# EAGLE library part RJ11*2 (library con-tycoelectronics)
RJ11 (Style 1 Shield / Style 2 Shield) Source: www.tycoelectronics.com .. ENG_DS_1654001_1099_RJ_L_0507.pdf
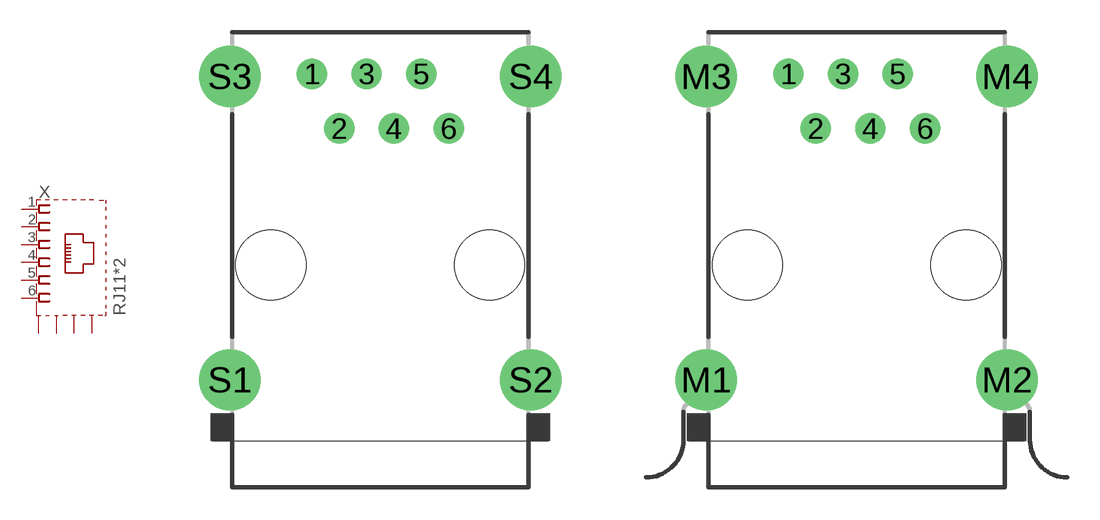
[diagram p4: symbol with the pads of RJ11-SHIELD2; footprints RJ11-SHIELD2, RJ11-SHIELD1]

Designator prefix X

## RJ11-2LC2-S (MPN: RJ11-2LC2-S; OC_FARNELL: unknown; OC_NEWARK: 16R6077), RJ11-4L2-S (MF: TYCO ELECTRONICS; MPN: RJ11-4L2-S; OC_FARNELL: unknown; OC_NEWARK: 50F8855), RJ11-4LC2-S (OC_FARNELL: unknown; OC_NEWARK: unknown), RJ11-6L2-S (MF: TYCO ELECTRONICS; MPN: RJ11-6L2-S=F9181; OC_FARNELL: unknown; OC_NEWARK: 80K4730), RJ11-6LC2-S (MPN: RJ11-6LC2-S; OC_FARNELL: unknown; OC_NEWARK: 16R6086), RJ11-6LCT2-S (MF: TYCO ELECTRONICS; MPN: RJ11-6LCT2-S.; OC_FARNELL: unknown; OC_NEWARK: 91F7257)  [RJ11-SHIELD2]
1  1  pas
2  2  pas
3  3  pas
4  4  pas
5  5  pas
6  6  pas
S1  S  pas
S2  S  pas
S3  S  pas
S4  S  pas

## RJ11-2LC2-B (OC_FARNELL: unknown; OC_NEWARK: unknown), RJ11-4L2-B (MF: TYCO ELECTRONICS; MPN: RJ11-4L2-B; OC_FARNELL: unknown; OC_NEWARK: 50F8856), RJ11-4LC2-B (MPN: RJ11-4LC2-B; OC_FARNELL: unknown; OC_NEWARK: 21M5804), RJ11-6L2-B (MPN: RJ11-6L2-B; OC_FARNELL: unknown; OC_NEWARK: 10M8526), RJ11-6LC2-B (MPN: RJ11-6LC2-B; OC_FARNELL: unknown; OC_NEWARK: 16R6085), RJ11-6LCT2-B (MPN: RJ11-6LCT2-B; OC_FARNELL: unknown; OC_NEWARK: 16R6083)  [RJ11-SHIELD2]
Pads as for RJ11-SHIELD2

## RJ11-2LC21-S (OC_FARNELL: unknown; OC_NEWARK: unknown), RJ11-4L21-S (OC_FARNELL: unknown; OC_NEWARK: unknown), RJ11-4LC21-S (OC_FARNELL: unknown; OC_NEWARK: unknown), RJ11-6L21-S (OC_FARNELL: unknown; OC_NEWARK: unknown), RJ11-6LC21-S (OC_FARNELL: unknown; OC_NEWARK: unknown), RJ11-6LCT21-S (OC_FARNELL: unknown; OC_NEWARK: unknown)  [RJ11-SHIELD1]
1  1  pas
2  2  pas
3  3  pas
4  4  pas
5  5  pas
6  6  pas
M1  S  pas
M2  S  pas
M3  S  pas
M4  S  pas

## RJ11-2LC21-B (OC_FARNELL: unknown; OC_NEWARK: unknown), RJ11-4L21-B (OC_FARNELL: unknown; OC_NEWARK: unknown), RJ11-4LC21-B (OC_FARNELL: unknown; OC_NEWARK: unknown), RJ11-6L21-B (OC_FARNELL: unknown; OC_NEWARK: unknown), RJ11-6LC21-B (OC_FARNELL: unknown; OC_NEWARK: unknown), RJ11-6LCT21-B (OC_FARNELL: unknown; OC_NEWARK: unknown)  [RJ11-SHIELD1]
Pads as for RJ11-SHIELD1

## Footprint RJ11-SHIELD2 (pad centres in mm)
RJ11 Low Profile Shield Type 2 For all RJ11 N and Z Series Models Source: www.tycoelectronics.com .. ENG_DS_1654001_1099_RJ_L_0507.pdf
drill 0.9 pad 1.4 round: 1 -3.175,8.89; 2 -1.905,6.35; 3 -0.635,8.89; 4 0.635,6.35; 5 1.905,8.89; 6 3.175,6.35
drill 1.9 pad 2.5 round: S1 -6.985,-5.334; S2 6.985,-5.334; S3 -6.985,8.763; S4 6.985,8.763
hole 3.251 at -5.08,0
hole 3.251 at 5.08,0

## Footprint RJ11-SHIELD1 (pad centres in mm)
RJ11 Low Profile Shield Type 1 For all RJ11 N and Z Series Models Source: www.tycoelectronics.com .. ENG_DS_1654001_1099_RJ_L_0507.pdf
drill 0.9 pad 1.4 round: 1 -3.175,8.89; 2 -1.905,6.35; 3 -0.635,8.89; 4 0.635,6.35; 5 1.905,8.89; 6 3.175,6.35
drill 1.9 pad 2.5 round: M1 -6.985,-5.334; M2 6.985,-5.334; M3 -6.985,8.763; M4 6.985,8.763
hole 3.251 at -5.08,0
hole 3.251 at 5.08,0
